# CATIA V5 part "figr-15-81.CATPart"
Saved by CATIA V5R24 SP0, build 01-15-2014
Part number: Part1
Bounding box of the stored display mesh (mm): x -28.659 to 28.659, y -52 to 52, z 0 to 2
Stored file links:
  D:\KAVITA\CATIA V5-6R2014 Project_ Kavita\CATIA V5-6R2014_partfiles\Partfiles\c15_catia_v5-6r2014_prt\figr-15-81.CATPart
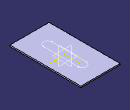
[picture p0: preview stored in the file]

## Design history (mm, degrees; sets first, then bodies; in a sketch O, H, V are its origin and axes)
SheetMetalParameters1: Thickness 2, BendRadius 4, KFactor 0.400515 {= log(min(100,max(20*SheetMetalParameters1.BendRadius,SheetMetalParameters1.Thickness)/SheetMetalParameters1.Thickness))/log(100)/2}, ReliefRadialLength 1, ReliefAxialLength 2, MinimumBendRadius 0
Body1 (main body)
  Sketch1 on xy-plane, origin (0, 0, 0), H (1, 0, 0), V (0, 1, 0)
    line L1 (28.6588, 52) -> (28.6588, -52)
    line L2 (28.6588, -52) -> (-28.6588, -52)
    line L3 (-28.6588, -52) -> (-28.6588, 52)
    line L4 (-28.6588, 52) -> (28.6588, 52)
    vertical: L1 V, L3 V
    horizontal: L2 H, L4 H
    equidistance: L1 L3 O, L2 L4 O
  Wall1: Thickness 2, Profile Sketch1, OffsetValue 0
  Sketch2 on face of Wall1, origin (0, 0, 2), H (1, 0, 0), V (0, 1, 0)
    construction line L1 (0, 25.3065) -> (0, -25.5921)
    point P1 (0, 25.3065)
    line L2 (6, 25.3065) -> (6, -25.5921)
    line L3 (-6, -25.5921) -> (-6, 25.3065)
    arc A1 centre (0, -25.5921) radius 6 from (6, -25.5921) to (-6, -25.5921) cw
    arc A2 centre (0, 25.3065) radius 6 from (-6, 25.3065) to (6, 25.3065) cw
    distance L1 L2 = 6
    coincidence: P1 V
    vertical: L1 V
    tangency: A1 L2, A2 L2, A1 L3, A2 L3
